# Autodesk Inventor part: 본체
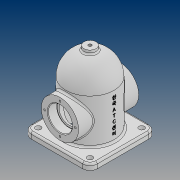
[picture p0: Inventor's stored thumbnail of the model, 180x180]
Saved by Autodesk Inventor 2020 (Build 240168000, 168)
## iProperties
Created: 2021-08
Part Number: 본체
Material: 일반
Document SubType Name: Modeling
Designer: PC312-
Density: 1 g/cm^3
Appearance: 기본값
Mass: 320.706 g
Surface Area: 800.755 cm^2
Volume: 320.706 cm^3
Author: PC312-
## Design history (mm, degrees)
sketch "스케치1"
  geometry: L1 (0, 0)-(129, 0); L2 (84, 40)-(0, 40); L3 (0, 40)-(0, 32); L4 (0, 32)-(84, 32); L5 (129, 0)-(129, 10); L6 (129, 10)-(122.73, 10); A1 r 40 centre (84, 0) between (122.73, 10) and (84, 40); A2 r 32 centre (84, 0) between (116, 0) and (84, 32)
  constraints: 13 end point, 4 horizontal, 4 point on circle, 3 point on line, 2 centre point, 2 vertical, 2 vertical alignment, 1 coincident
  dimensions: "d1" = 80 diameter of A1; "d2" = 64 diameter of A2; "d10" = 129 distance of L1.start L1.end; "d11" = 20 diameter of L6 L1; "d12" = 84 distance of L1.start A1.centre
revolve "회전1" sketch "스케치1" stored, may be unused: angle "d3" = 90 deg
sketch "스케치2"
  geometry: L1 (55, -55)-(-55, -55); L2 (-55, -55)-(-55, 55); L3 (-55, 55)-(55, 55); L4 (55, 55)-(55, -55); C1 r 40 at (0, 0) reference; 1 further point
  constraints: 8 end point, 2 parallel, 1 horizontal, 1 perpendicular
  dimensions: "d4" = 110 distance of L1.start L1.end; "d5" = 110 distance of L1.end L2.end; "d6" = 55 distance from line of point (0, 0) L1; "d7" = 55 distance from line of point (0, 0) L4
extrude "돌출1" join sketch "스케치2" distance "d8" = 10; taper "d9" = 0 deg
node "작업 평면1"
sketch "스케치3"
  geometry: L1 (-55, 0)-(55, 0) reference; C1 r 31 at (0, 48); 2 further points
  constraints: 1 centre point, 1 midpoint, 1 vertical alignment
  dimensions: "d14" = 62 diameter of C1; "d15" = 48 distance from line of L1 C1.centre
extrude "돌출2" join sketch "스케치3" stored distance "d16" = 10; taper "d17" = 0 deg
sketch "스케치4"
  geometry: C1 r 20 at (0, 0); C2 r 31 at (0, 0) reference; 1 further point
  constraints: 1 centre point, 1 concentric
  dimensions: "d18" = 40 diameter of C1
extrude "돌출3" cut sketch "스케치4" distance "d19" = 15; taper "d20" = 0 deg
sketch "스케치5"
  geometry: L1 (-55, -48)-(55, -48) reference; C1 r 20 at (0, 0) reference; 3 further points
  constraints: 1 midpoint, 1 vertical alignment
  dimensions: "d21" = 25.5 distance of C1.centre point (0, 25.5)
hole "구멍1" sketch "스케치5" at (0, 25.5) diameter "d22" = 3.242; stored, may be unused: countersink angle "d26" = 90 deg, drill point angle "d28" = 118 deg; dims "d23" = 8, "d24" = 4, "d25" = 2, "d27" = 10
sketch "스케치6"
  geometry: C1 r 16.5 at (0, 0); C2 r 20 at (0, 0) reference; 1 further point
  constraints: 1 centre point, 1 concentric
  dimensions: "d32" = 33 diameter of C1
extrude "돌출4" cut sketch "스케치6" extent not by distance; stored distance "d33" = 15; taper "d34" = 0 deg
sketch "스케치7"
  geometry: C1 r 10 at (0, 0) reference; 2 further points
  constraints: 1 coincident
hole "구멍2" sketch "스케치7" at (0, 0) diameter "d35" = 5.1881; stored, may be unused: countersink angle "d39" = 90 deg, drill point angle "d41" = 118 deg; dims "d36" = 12, "d37" = 4, "d38" = 2, "d40" = 20
fillet "모깎기1" dims "d42" = 12
sketch "스케치8"
  geometry: C1 r 4.5 at (-43, 43); A1 r 12 centre (-43, 43) between (-43, 55) and (-55, 43) reference; 1 further point
  constraints: 1 centre point, 1 concentric
  dimensions: "d43" = 9 diameter of C1
extrude "돌출5" cut sketch "스케치8" extent not by distance; stored distance "d44" = 15; taper "d45" = 0 deg
fillet "모깎기2" dims "d52" = 0.3
fillet "모깎기3" dims "d53" = 3
chamfer "모따기1" distance "d54" = 1; stored, may be unused: second distance "d55" = 2, angle "d56" = 45 deg
node "작업 평면2"
sketch "스케치9"
  geometry: L1 (0, 43)-(0, -43) reference; 3 further points
  constraints: 1 horizontal alignment, 1 midpoint, 1 other
  dimensions: "d58" = 48 distance from line of L1 point (48, 0)
feature "엠보싱1" sketch "스케치9" dims "d14" = 62, "d15" = 48, "d59" = 0.5, "d60" = 0
node "솔리드1"
pattern_circular "원형 패턴1" dims angle "d30" = 360 deg
mirror "미러1"
pattern_linear "직사각형 패턴1" dims "d48" = 86, "d51" = 86
feature "A9D066F2-1C7D-4E18-AEED-F7BC21143FA4" dims "d22" = 3.242, "d23" = 8, "d24" = 4, "d25" = 2, "d26" = 90 deg, "d27" = 10, "d28" = 118 deg
other parameters: "d57" = 53.25
